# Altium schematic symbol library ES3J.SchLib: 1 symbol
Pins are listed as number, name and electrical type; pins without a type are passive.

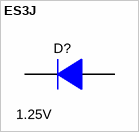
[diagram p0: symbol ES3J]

## ES3J
designator D?  value 1.25V  (hidden comment: ES3J)
DIODE ULTRAFAST 600V 3A DO-214AB; Manufacturer: Fairchild Semiconductor; Alternate Manufacturer: Any; Alternate PartNumber: Equivalent; U/M: EA; Vf_V: 1.25; Io_A: 3; Vr_V: 600; TJmax_C: 175
signal-integrity model Diode
footprint DO-214AB (FAIRCHILD DO-0214AB)
footprint SMC (Molded Diode, 2-Leads, Body 6.9x5.8mm, IPC Medium Density, based on OnSemi component dimensions and land patterns)
pins: 1 K, 2 A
